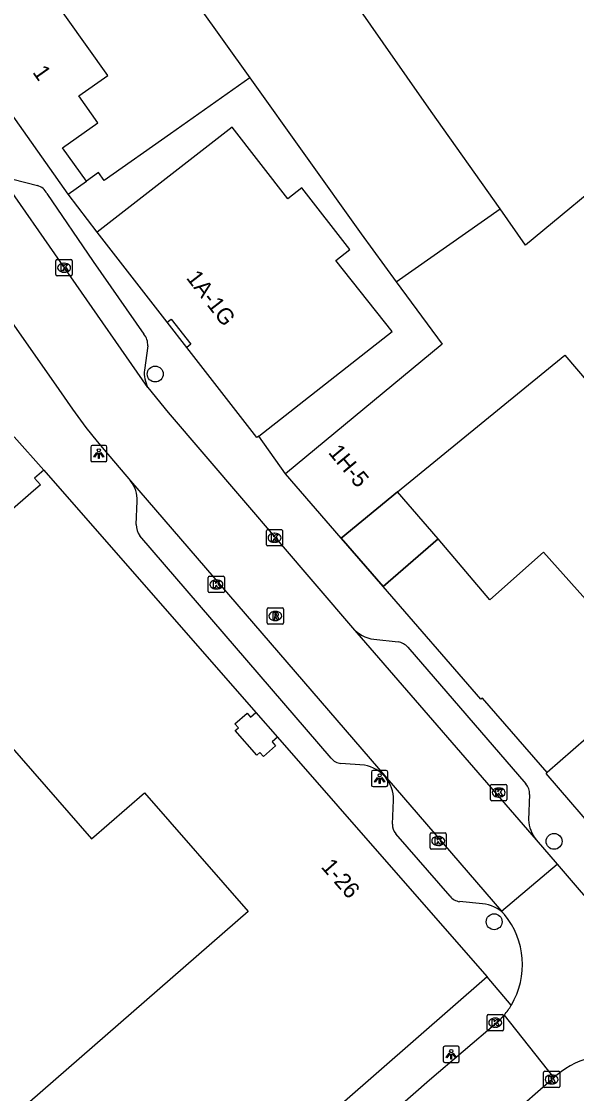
# Model space of a CAD drawing. Extents: x 160664 to 161506, y 382245 to 383288.
# Drawn here: x 160818.4 to 160852.6, y 383089.2 to 383155.3 of the extents above; entities that cross this region are included whole.
import ezdxf

# ---------------------------------------------------------------- set-up
doc = ezdxf.new("R2010")
doc.units = 0
for name, color, linetype in [('IMGEO_Boom', 7, 'Continuous'), ('IMGEO_Kolk', 7, 'Continuous'), ('IMGEO_Lichtpunt', 7, 'Continuous'), ('IMGEO_Pand', 7, 'Continuous'), ('IMGEO_Pand_nummerreeks', 7, 'Continuous'), ('IMGEO_Pand_overbouw', 7, 'Continuous'), ('IMGEO_Rijbaan_lokaal_open', 7, 'Continuous'), ('IMGEO_Rioolput', 7, 'Continuous'), ('IMGEO_Voetpad_open', 7, 'Continuous')]:
    doc.layers.add(name, color=color, linetype=linetype)

msp = doc.modelspace()

# ---------------------------------------------------------------- linework, layer by layer
at = {"layer": 'IMGEO_Boom'}
for centre in [(160826.619, 383133.522), (160851.188, 383104.717), (160847.496, 383099.762)]:
    msp.add_circle(centre, 0.489, dxfattribs=at)
at = {"layer": 'IMGEO_Kolk'}
for p, q in [((160820.503, 383139.649), (160820.503, 383140.501)), ((160820.578, 383140.575), (160821.43, 383140.575)), ((160820.991, 383140.355), (160821.016, 383140.355)), ((160821.504, 383140.501), (160821.504, 383139.649)), ((160821.014, 383139.795), (160820.989, 383139.795)), ((160821.43, 383139.575), (160820.578, 383139.575)), ((160833.468, 383123.005), (160833.468, 383123.857)), ((160833.543, 383123.931), (160834.395, 383123.931)), ((160834.469, 383123.857), (160834.469, 383123.005)), ((160833.979, 383123.151), (160833.954, 383123.151)), ((160833.956, 383123.711), (160833.981, 383123.711)), ((160834.395, 383122.931), (160833.543, 383122.931)), ((160829.887, 383120.128), (160829.887, 383120.98)), ((160829.962, 383121.054), (160830.814, 383121.054)), ((160830.375, 383120.834), (160830.4, 383120.834)), ((160830.888, 383120.98), (160830.888, 383120.128)), ((160830.814, 383120.054), (160829.962, 383120.054)), ((160830.398, 383120.274), (160830.373, 383120.274)), ((160847.275, 383107.299), (160847.275, 383108.151)), ((160847.35, 383108.225), (160848.202, 383108.225)), ((160847.763, 383108.005), (160847.788, 383108.005)), ((160848.276, 383108.151), (160848.276, 383107.299)), ((160847.786, 383107.445), (160847.761, 383107.445)), ((160848.202, 383107.225), (160847.35, 383107.225)), ((160843.549, 383104.316), (160843.549, 383105.168)), ((160843.624, 383105.242), (160844.476, 383105.242)), ((160844.037, 383105.022), (160844.062, 383105.022)), ((160844.55, 383105.168), (160844.55, 383104.316)), ((160844.476, 383104.242), (160843.624, 383104.242)), ((160844.06, 383104.462), (160844.035, 383104.462)), ((160847.138, 383094.042), (160847.99, 383094.042)), ((160847.063, 383093.116), (160847.063, 383093.968)), ((160847.551, 383093.822), (160847.576, 383093.822)), ((160848.064, 383093.968), (160848.064, 383093.116)), ((160847.99, 383093.042), (160847.138, 383093.042)), ((160847.574, 383093.262), (160847.549, 383093.262)), ((160850.538, 383089.616), (160850.538, 383090.468)), ((160850.613, 383090.542), (160851.465, 383090.542)), ((160851.026, 383090.322), (160851.051, 383090.322)), ((160851.539, 383090.468), (160851.539, 383089.616)), ((160851.465, 383089.542), (160850.613, 383089.542)), ((160851.049, 383089.762), (160851.024, 383089.762))]:
    msp.add_line(p, q, dxfattribs=at)
for points in [[(160820.503, 383139.649), (160820.503, 383140.501)], [(160820.578, 383140.575), (160821.43, 383140.575)], [(160821.504, 383140.501), (160821.504, 383139.649)], [(160820.824, 383140.275), (160820.947, 383140.275), (160820.947, 383140.124), (160821.077, 383140.275), (160821.241, 383140.275), (160821.095, 383140.124), (160821.248, 383139.875), (160821.096, 383139.875), (160821.011, 383140.039), (160820.947, 383139.972), (160820.947, 383139.875), (160820.824, 383139.875), (160820.824, 383140.275)], [(160821.43, 383139.575), (160820.578, 383139.575)], [(160833.468, 383123.005), (160833.468, 383123.857)], [(160833.543, 383123.931), (160834.395, 383123.931)], [(160834.469, 383123.857), (160834.469, 383123.005)], [(160833.789, 383123.631), (160833.912, 383123.631), (160833.912, 383123.48), (160834.042, 383123.631), (160834.206, 383123.631), (160834.06, 383123.48), (160834.213, 383123.231), (160834.061, 383123.231), (160833.976, 383123.395), (160833.912, 383123.328), (160833.912, 383123.231), (160833.789, 383123.231), (160833.789, 383123.631)], [(160834.395, 383122.931), (160833.543, 383122.931)], [(160829.887, 383120.128), (160829.887, 383120.98)], [(160829.962, 383121.054), (160830.814, 383121.054)], [(160830.208, 383120.754), (160830.331, 383120.754), (160830.331, 383120.603), (160830.461, 383120.754), (160830.625, 383120.754), (160830.479, 383120.603), (160830.632, 383120.354), (160830.48, 383120.354), (160830.395, 383120.518), (160830.331, 383120.451), (160830.331, 383120.354), (160830.208, 383120.354), (160830.208, 383120.754)], [(160830.888, 383120.98), (160830.888, 383120.128)], [(160830.814, 383120.054), (160829.962, 383120.054)], [(160847.275, 383107.299), (160847.275, 383108.151)], [(160847.35, 383108.225), (160848.202, 383108.225)], [(160847.596, 383107.925), (160847.719, 383107.925), (160847.719, 383107.774), (160847.849, 383107.925), (160848.013, 383107.925), (160847.867, 383107.774), (160848.02, 383107.525), (160847.868, 383107.525), (160847.783, 383107.689), (160847.719, 383107.622), (160847.719, 383107.525), (160847.596, 383107.525), (160847.596, 383107.925)], [(160848.276, 383108.151), (160848.276, 383107.299)], [(160848.202, 383107.225), (160847.35, 383107.225)], [(160843.549, 383104.316), (160843.549, 383105.168)], [(160843.624, 383105.242), (160844.476, 383105.242)], [(160843.87, 383104.942), (160843.993, 383104.942), (160843.993, 383104.791), (160844.123, 383104.942), (160844.287, 383104.942), (160844.141, 383104.791), (160844.294, 383104.542), (160844.142, 383104.542), (160844.057, 383104.706), (160843.993, 383104.639), (160843.993, 383104.542), (160843.87, 383104.542), (160843.87, 383104.942)], [(160844.55, 383105.168), (160844.55, 383104.316)], [(160844.476, 383104.242), (160843.624, 383104.242)], [(160847.138, 383094.042), (160847.99, 383094.042)], [(160847.063, 383093.116), (160847.063, 383093.968)], [(160847.384, 383093.742), (160847.507, 383093.742), (160847.507, 383093.591), (160847.637, 383093.742), (160847.801, 383093.742), (160847.655, 383093.591), (160847.808, 383093.342), (160847.656, 383093.342), (160847.571, 383093.506), (160847.507, 383093.439), (160847.507, 383093.342), (160847.384, 383093.342), (160847.384, 383093.742)], [(160848.064, 383093.968), (160848.064, 383093.116)], [(160847.99, 383093.042), (160847.138, 383093.042)], [(160850.538, 383089.616), (160850.538, 383090.468)], [(160850.613, 383090.542), (160851.465, 383090.542)], [(160850.859, 383090.242), (160850.982, 383090.242), (160850.982, 383090.091), (160851.112, 383090.242), (160851.276, 383090.242), (160851.13, 383090.091), (160851.283, 383089.842), (160851.131, 383089.842), (160851.046, 383090.006), (160850.982, 383089.939), (160850.982, 383089.842), (160850.859, 383089.842), (160850.859, 383090.242)], [(160851.539, 383090.468), (160851.539, 383089.616)], [(160851.465, 383089.542), (160850.613, 383089.542)]]:
    msp.add_lwpolyline(points, dxfattribs=at)
for centre, start, end in [((160820.58, 383140.499), 91.55205, 178.44795), ((160820.58, 383140.499), 91.55205, 178.44795), ((160821.428, 383140.499), 1.55205, 88.44795), ((160821.428, 383140.499), 1.55205, 88.44795), ((160820.58, 383139.651), 181.55205, 268.44795), ((160820.58, 383139.651), 181.55205, 268.44795), ((160821.428, 383139.651), 271.55205, 358.44795), ((160821.428, 383139.651), 271.55205, 358.44795), ((160833.545, 383123.855), 91.55205, 178.44795), ((160833.545, 383123.855), 91.55205, 178.44795), ((160834.393, 383123.855), 1.55205, 88.44795), ((160834.393, 383123.855), 1.55205, 88.44795), ((160833.545, 383123.007), 181.55205, 268.44795), ((160833.545, 383123.007), 181.55205, 268.44795), ((160834.393, 383123.007), 271.55205, 358.44795), ((160834.393, 383123.007), 271.55205, 358.44795), ((160829.964, 383120.978), 91.55205, 178.44795), ((160829.964, 383120.978), 91.55205, 178.44795), ((160830.812, 383120.978), 1.55205, 88.44795), ((160830.812, 383120.978), 1.55205, 88.44795), ((160829.964, 383120.13), 181.55205, 268.44795), ((160829.964, 383120.13), 181.55205, 268.44795), ((160830.812, 383120.13), 271.55205, 358.44795), ((160830.812, 383120.13), 271.55205, 358.44795), ((160847.352, 383108.149), 91.55205, 178.44795), ((160847.352, 383108.149), 91.55205, 178.44795), ((160848.2, 383108.149), 1.55205, 88.44795), ((160848.2, 383108.149), 1.55205, 88.44795), ((160847.352, 383107.301), 181.55205, 268.44795), ((160847.352, 383107.301), 181.55205, 268.44795), ((160848.2, 383107.301), 271.55205, 358.44795), ((160848.2, 383107.301), 271.55205, 358.44795), ((160843.626, 383105.166), 91.55205, 178.44795), ((160843.626, 383105.166), 91.55205, 178.44795), ((160844.474, 383105.166), 1.55205, 88.44795), ((160844.474, 383105.166), 1.55205, 88.44795), ((160843.626, 383104.318), 181.55205, 268.44795), ((160843.626, 383104.318), 181.55205, 268.44795), ((160844.474, 383104.318), 271.55205, 358.44795), ((160844.474, 383104.318), 271.55205, 358.44795), ((160847.14, 383093.966), 91.55205, 178.44795), ((160847.14, 383093.966), 91.55205, 178.44795), ((160847.988, 383093.966), 1.55205, 88.44795), ((160847.988, 383093.966), 1.55205, 88.44795), ((160847.14, 383093.118), 181.55205, 268.44795), ((160847.14, 383093.118), 181.55205, 268.44795), ((160847.988, 383093.118), 271.55205, 358.44795), ((160847.988, 383093.118), 271.55205, 358.44795), ((160850.615, 383090.466), 91.55205, 178.44795), ((160850.615, 383090.466), 91.55205, 178.44795), ((160851.463, 383090.466), 1.55205, 88.44795), ((160851.463, 383090.466), 1.55205, 88.44795), ((160850.615, 383089.618), 181.55205, 268.44795), ((160850.615, 383089.618), 181.55205, 268.44795), ((160851.463, 383089.618), 271.55205, 358.44795), ((160851.463, 383089.618), 271.55205, 358.44795)]:
    msp.add_arc(centre, 0.0765, start, end, dxfattribs=at)
for centre, major_axis, ratio, start_param, end_param in [((160820.99, 383140.075), (-0.387, 0.002), 0.722429, 4.712389, 7.853982), ((160821.015, 383140.075), (-0.39, 0.002), 0.717154, 1.570796, 4.712389), ((160833.955, 383123.431), (-0.387, 0.002), 0.722429, 4.712389, 7.853982), ((160833.98, 383123.431), (-0.39, 0.002), 0.717154, 1.570796, 4.712389), ((160830.374, 383120.554), (-0.387, 0.002), 0.722429, 4.712389, 7.853982), ((160830.399, 383120.554), (-0.39, 0.002), 0.717154, 1.570796, 4.712389), ((160847.762, 383107.725), (-0.387, 0.002), 0.722429, 4.712389, 7.853982), ((160847.787, 383107.725), (-0.39, 0.002), 0.717154, 1.570796, 4.712389), ((160844.036, 383104.742), (-0.387, 0.002), 0.722429, 4.712389, 7.853982), ((160844.061, 383104.742), (-0.39, 0.002), 0.717154, 1.570796, 4.712389), ((160847.55, 383093.542), (-0.387, 0.002), 0.722429, 4.712389, 7.853982), ((160847.575, 383093.542), (-0.39, 0.002), 0.717154, 1.570796, 4.712389), ((160851.025, 383090.042), (-0.387, 0.002), 0.722429, 4.712389, 7.853982), ((160851.05, 383090.042), (-0.39, 0.002), 0.717154, 1.570796, 4.712389)]:
    msp.add_ellipse(centre, major_axis=major_axis, ratio=ratio, start_param=start_param, end_param=end_param, dxfattribs=at)
at = {"layer": 'IMGEO_Lichtpunt'}
for p, q in [((160823.549, 383129.118), (160822.741, 383129.118)), ((160823.549, 383129.118), (160822.741, 383129.118)), ((160822.647, 383129.023), (160822.647, 383128.216)), ((160822.647, 383129.023), (160822.647, 383128.216)), ((160823.643, 383128.216), (160823.643, 383129.023)), ((160823.643, 383128.216), (160823.643, 383129.023)), ((160822.741, 383128.122), (160823.549, 383128.122)), ((160822.741, 383128.122), (160823.549, 383128.122)), ((160839.944, 383108.991), (160839.944, 383108.184)), ((160839.944, 383108.991), (160839.944, 383108.184)), ((160840.846, 383109.086), (160840.038, 383109.086)), ((160840.846, 383109.086), (160840.038, 383109.086)), ((160840.94, 383108.184), (160840.94, 383108.991)), ((160840.94, 383108.184), (160840.94, 383108.991)), ((160840.038, 383108.09), (160840.846, 383108.09)), ((160840.038, 383108.09), (160840.846, 383108.09)), ((160845.257, 383092.088), (160844.449, 383092.088)), ((160845.257, 383092.088), (160844.449, 383092.088)), ((160844.355, 383091.993), (160844.355, 383091.186)), ((160844.355, 383091.993), (160844.355, 383091.186)), ((160845.351, 383091.186), (160845.351, 383091.993)), ((160845.351, 383091.186), (160845.351, 383091.993)), ((160844.449, 383091.092), (160845.257, 383091.092)), ((160844.449, 383091.092), (160845.257, 383091.092))]:
    msp.add_line(p, q, dxfattribs=at)
for points in [[(160823.021, 383128.687), (160823.06, 383128.659), (160822.872, 383128.397), (160822.834, 383128.424), (160823.021, 383128.687)], [(160823.123, 383128.639), (160823.17, 383128.639), (160823.17, 383128.317), (160823.123, 383128.317), (160823.123, 383128.639)], [(160823.233, 383128.659), (160823.271, 383128.686), (160823.458, 383128.424), (160823.419, 383128.396), (160823.233, 383128.659)], [(160840.318, 383108.655), (160840.357, 383108.627), (160840.169, 383108.365), (160840.131, 383108.392), (160840.318, 383108.655)], [(160840.42, 383108.607), (160840.467, 383108.607), (160840.467, 383108.285), (160840.42, 383108.285), (160840.42, 383108.607)], [(160840.53, 383108.627), (160840.568, 383108.654), (160840.755, 383108.392), (160840.716, 383108.364), (160840.53, 383108.627)], [(160844.729, 383091.657), (160844.768, 383091.629), (160844.58, 383091.367), (160844.542, 383091.394), (160844.729, 383091.657)], [(160844.831, 383091.609), (160844.878, 383091.609), (160844.878, 383091.287), (160844.831, 383091.287), (160844.831, 383091.609)], [(160844.941, 383091.629), (160844.979, 383091.656), (160845.166, 383091.394), (160845.127, 383091.366), (160844.941, 383091.629)]]:
    msp.add_lwpolyline(points, dxfattribs=at)
for centre in [(160823.146, 383128.821), (160840.443, 383108.789), (160844.854, 383091.791)]:
    msp.add_circle(centre, 0.0994, dxfattribs=at)
for centre, start, end in [((160822.741, 383129.023), 90, 180), ((160822.741, 383129.023), 90, 180), ((160823.549, 383129.023), 0, 90), ((160823.549, 383129.023), 0, 90), ((160822.741, 383128.216), 180, 270), ((160822.741, 383128.216), 180, 270), ((160823.549, 383128.216), 270, 0), ((160823.549, 383128.216), 270, 360), ((160840.038, 383108.991), 90, 180), ((160840.038, 383108.991), 90, 180), ((160840.846, 383108.991), 0, 90), ((160840.846, 383108.991), 0, 90), ((160840.038, 383108.184), 180, 270), ((160840.038, 383108.184), 180, 270), ((160840.846, 383108.184), 270, 0), ((160840.846, 383108.184), 270, 360), ((160844.449, 383091.993), 90, 180), ((160844.449, 383091.993), 90, 180), ((160845.257, 383091.993), 0, 90), ((160845.257, 383091.993), 0, 90), ((160844.449, 383091.186), 180, 270), ((160844.449, 383091.186), 180, 270), ((160845.257, 383091.186), 270, 0), ((160845.257, 383091.186), 270, 360)]:
    msp.add_arc(centre, 0.0946, start, end, dxfattribs=at)
at = {"layer": 'IMGEO_Pand'}
for points in [[(160824.34, 383163.154), (160832.439, 383151.785)], [(160822.38, 383145.405), (160820.912, 383147.471), (160823.084, 383149.009), (160821.915, 383150.662), (160823.694, 383151.92), (160818.613, 383159.104)], [(160847.865, 383143.697), (160843.625, 383149.714), (160840.653, 383153.931), (160838.375, 383157.23)], [(160821.254, 383144.609), (160814.35, 383154.373)], [(160832.439, 383151.785), (160827.563, 383148.336), (160823.48, 383145.448), (160823.133, 383145.938), (160822.38, 383145.405)], [(160832.439, 383151.785), (160839.295, 383142.162), (160841.468, 383139.204)], [(160832.992, 383129.701), (160841.22, 383136.153), (160837.738, 383140.525), (160838.606, 383141.201), (160835.646, 383145.005), (160834.778, 383144.329), (160831.351, 383148.733), (160823.035, 383142.262)], [(160862.78, 383119.438), (160871.792, 383127.293), (160855.494, 383146.477), (160849.437, 383141.466), (160847.865, 383143.697)], [(160821.254, 383144.609), (160822.38, 383145.405)], [(160841.468, 383139.204), (160847.865, 383143.697)], [(160827.356, 383136.717), (160823.035, 383142.262)], [(160841.468, 383139.204), (160844.287, 383135.367), (160834.654, 383127.38)], [(160827.356, 383136.717), (160827.608, 383136.913), (160828.82, 383135.359), (160828.567, 383135.162)], [(160832.992, 383129.701), (160832.886, 383129.618), (160828.567, 383135.162)], [(160838.066, 383123.41), (160841.544, 383126.254), (160851.849, 383134.678), (160855.448, 383130.467), (160860.986, 383123.842), (160859.189, 383122.242), (160859.707, 383121.66), (160855.036, 383117.501), (160850.542, 383122.549), (160847.23, 383119.601), (160844.049, 383123.372), (160840.66, 383120.426)], [(160819.762, 383127.606), (160819.19, 383127.107), (160819.545, 383126.7), (160818.954, 383126.185), (160810.516, 383118.826), (160822.694, 383104.864), (160825.95, 383107.704), (160832.337, 383100.4), (160801.258, 383073.294), (160801.519, 383072.995), (160807.956, 383065.608), (160808.556, 383064.92), (160808.34, 383064.726), (160809.442, 383063.5)], [(160819.762, 383127.606), (160832.816, 383112.657)], [(160838.066, 383123.41), (160834.654, 383127.38)], [(160850.763, 383108.963), (160846.774, 383113.543), (160846.678, 383113.478), (160840.66, 383120.426)], [(160862.78, 383119.438), (160850.763, 383108.963)], [(160834.141, 383111.138), (160833.817, 383110.855), (160834.034, 383110.607), (160833.281, 383109.948), (160833.064, 383110.197), (160832.876, 383110.032), (160831.551, 383111.552), (160831.739, 383111.716), (160831.522, 383111.965), (160832.275, 383112.623), (160832.492, 383112.374), (160832.816, 383112.657)], [(160834.141, 383111.138), (160841.583, 383102.623), (160847.06, 383096.364)], [(160854.374, 383104.619), (160850.691, 383108.893), (160850.763, 383108.963)], [(160847.06, 383096.364), (160809.442, 383063.5)]]:
    msp.add_lwpolyline(points, dxfattribs=at)
at = {"layer": 'IMGEO_Pand_overbouw'}
msp.add_lwpolyline([(160841.544, 383126.254), (160838.066, 383123.41), (160840.66, 383120.426), (160844.049, 383123.372)], close=True, dxfattribs=at)
at = {"layer": 'IMGEO_Rijbaan_lokaal_open'}
for points in [[(160826.168, 383132.701), (160816.664, 383146.344)], [(160817.769, 383136.732), (160820.684, 383132.561), (160821.531, 383131.367), (160822.35, 383130.236), (160823.047, 383129.367), (160823.481, 383128.851), (160825.101, 383126.939)], [(160826.168, 383132.701), (160827.416, 383131.144), (160838.779, 383117.869)], [(160825.101, 383126.939), (160847.955, 383100.412)], [(160838.779, 383117.869), (160850.081, 383104.819)], [(160850.081, 383104.819), (160851.37, 383103.314)], [(160847.955, 383100.412), (160851.37, 383103.314)], [(160851.37, 383103.314), (160857.45, 383096.213)], [(160847.955, 383100.412), (160848.126, 383100.214)], [(160775.693, 383030.755), (160776.565, 383031.484), (160805.468, 383056.726), (160810.456, 383061.058), (160822.843, 383071.893), (160841.492, 383088.25), (160843.505, 383090.016), (160847.663, 383093.554), (160847.879, 383093.733), (160848.095, 383093.974), (160848.126, 383094.012)], [(160851.178, 383090.157), (160848.126, 383094.012)], [(160820.707, 383063.65), (160822.207, 383064.969), (160826.577, 383068.705), (160844.711, 383084.462), (160846.819, 383086.338), (160851.039, 383090.042), (160851.178, 383090.157)], [(160851.378, 383090.321), (160851.203, 383090.177), (160851.178, 383090.157)]]:
    msp.add_lwpolyline(points, dxfattribs=at)
for centre, radius, start, end in [((160844.35, 383097.113), 4.887, 329.38306, 39.39397), ((160844.265, 383097.175), 4.991, 320.67655, 329.26405), ((160854.434, 383086.816), 4.65, 66.85453, 131.08711)]:
    msp.add_arc(centre, radius, start, end, dxfattribs=at)
at = {"layer": 'IMGEO_Rioolput'}
for p, q in [((160833.517, 383118.182), (160833.517, 383119.034)), ((160833.592, 383119.108), (160834.444, 383119.108)), ((160834.005, 383118.888), (160834.03, 383118.888)), ((160834.518, 383119.034), (160834.518, 383118.182)), ((160834.444, 383118.108), (160833.592, 383118.108)), ((160834.028, 383118.328), (160834.003, 383118.328))]:
    msp.add_line(p, q, dxfattribs=at)
for points in [[(160833.517, 383118.182), (160833.517, 383119.034)], [(160833.592, 383119.108), (160834.444, 383119.108)], [(160834.106, 383118.806), (160833.854, 383118.808), (160833.854, 383118.408)], [(160833.854, 383118.408), (160833.978, 383118.408), (160833.978, 383118.57), (160833.989, 383118.57)], [(160834.032, 383118.727), (160833.978, 383118.727), (160833.978, 383118.646)], [(160833.978, 383118.646), (160834.03, 383118.646)], [(160834.036, 383118.541), (160834.107, 383118.408), (160834.247, 383118.408), (160834.182, 383118.534)], [(160834.518, 383119.034), (160834.518, 383118.182)], [(160834.444, 383118.108), (160833.592, 383118.108)]]:
    msp.add_lwpolyline(points, dxfattribs=at)
for centre, radius, start, end in [((160833.594, 383119.032), 0.0765, 91.55205, 178.44795), ((160833.594, 383119.032), 0.0765, 91.55205, 178.44795), ((160833.988, 383118.517), 0.0533, 26.02933, 88.69889), ((160834.014, 383118.835), 0.19, 274.7715, 282.96867), ((160834.038, 383118.631), 0.0964, 77.00612, 93.18647), ((160834.052, 383118.688), 0.0378, 276.66336, 79.67722), ((160834.105, 383118.696), 0.109, 350.36119, 89.41601), ((160834.103, 383118.696), 0.112, 277.58423, 350.98172), ((160834.087, 383118.481), 0.108, 29.51342, 73.79051), ((160834.442, 383119.032), 0.0765, 1.55205, 88.44795), ((160834.442, 383119.032), 0.0765, 1.55205, 88.44795), ((160833.594, 383118.184), 0.0765, 181.55205, 268.44795), ((160833.594, 383118.184), 0.0765, 181.55205, 268.44795), ((160834.442, 383118.184), 0.0765, 271.55205, 358.44795), ((160834.442, 383118.184), 0.0765, 271.55205, 358.44795)]:
    msp.add_arc(centre, radius, start, end, dxfattribs=at)
for centre, major_axis, ratio, start_param, end_param in [((160834.004, 383118.608), (-0.387, 0.002), 0.722429, 4.712389, 7.853982), ((160834.029, 383118.608), (-0.39, 0.002), 0.717154, 1.570796, 4.712389)]:
    msp.add_ellipse(centre, major_axis=major_axis, ratio=ratio, start_param=start_param, end_param=end_param, dxfattribs=at)
at = {"layer": 'IMGEO_Voetpad_open'}
for points in [[(160817.839, 383145.534), (160819.36, 383145.139)], [(160819.939, 383144.65), (160822.795, 383140.456), (160825.92, 383135.981)], [(160823.035, 383142.262), (160821.254, 383144.609)], [(160828.567, 383135.162), (160827.356, 383136.717)], [(160826.156, 383135.26), (160825.952, 383133.77)], [(160817.935, 383129.644), (160819.762, 383127.606)], [(160834.654, 383127.38), (160832.992, 383129.701)], [(160825.438, 383124.241), (160825.514, 383125.691)], [(160837.46, 383109.842), (160825.665, 383123.556)], [(160840.66, 383120.426), (160838.066, 383123.41)], [(160840.079, 383117.175), (160841.583, 383117.011)], [(160842.183, 383116.692), (160849.456, 383108.259)], [(160832.816, 383112.657), (160834.141, 383111.138)], [(160839.507, 383109.41), (160838.048, 383109.515)], [(160849.672, 383107.604), (160849.613, 383106.053)], [(160841.231, 383105.775), (160841.303, 383107.254)], [(160844.781, 383101.339), (160841.435, 383105.188)], [(160846.777, 383100.867), (160845.357, 383101)], [(160848.555, 383094.624), (160847.06, 383096.364)]]:
    msp.add_lwpolyline(points, dxfattribs=at)
for centre, radius, start, end in [((160819.151, 383144.305), 0.86, 23.66792, 75.96591), ((160825.183, 383135.341), 0.976, 355.26526, 40.98368), ((160827.86, 383133.599), 1.916, 174.88742, 207.95912), ((160823.589, 383125.746), 1.925, 358.34956, 38.27224), ((160826.682, 383124.273), 1.244, 181.47726, 215.19178), ((160840.351, 383119.249), 2.091, 221.27609, 262.53319), ((160841.361, 383115.869), 1.164, 45.02533, 78.9785), ((160838.193, 383110.469), 0.965, 220.50963, 261.33154), ((160839.145, 383107.283), 2.158, 359.23821, 80.35202), ((160848.726, 383107.655), 0.947, 356.90452, 39.5976), ((160851.703, 383106.14), 2.092, 182.381, 219.15791), ((160842.138, 383105.761), 0.907, 179.12131, 219.20642), ((160845.494, 383101.892), 0.903, 217.80036, 261.24247), ((160846.567, 383098.714), 2.164, 43.90501, 84.43524)]:
    msp.add_arc(centre, radius, start, end, dxfattribs=at)

# ---------------------------------------------------------------- texts
at = {"layer": 'IMGEO_Pand_nummerreeks'}
for s, rotation, p in [('1', 305.26364, (160819.029, 383152.121)), ('1A-1G', 307.6206, (160828.49, 383139.442)), ('1H-5', 309.74014, (160837.239, 383128.672)), ('1-26', 311.1678, (160836.792, 383103.122))]:
    msp.add_text(s, height=1, rotation=rotation, dxfattribs=at).set_placement(p)

doc.saveas('drawing.dxf')
